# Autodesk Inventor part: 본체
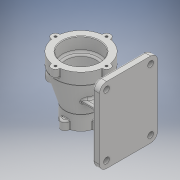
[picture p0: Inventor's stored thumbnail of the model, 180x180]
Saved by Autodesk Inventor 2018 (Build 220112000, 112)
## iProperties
Created: 2020-12
Part Number: 본체
Material: 일반
Document SubType Name: Modeling
Designer: home
Density: 1 g/cm^3
Appearance: 기본값
Author: home
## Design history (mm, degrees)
sketch "스케치1"
  geometry: L1 (0, 50)-(0, -50); L2 (32, 50)-(32, 30); L3 (29, 27)-(29, 27); L4 (26, 24)-(26, -17); L5 (23, -20)-(23, -20); L6 (20, -23)-(20, -50); L7 (32, 50)-(44, 50); L8 (44, 50)-(44, 30); L9 (20, -50)-(27.5, -50); L10 (27.5, -50)-(27.5, -25); L11 (27.5, -25)-(44, 30); A1 r 3 centre (29, 30) between (29, 27) and (32, 30); A2 r 3 centre (29, 24) between (29, 27) and (26, 24); A3 r 3 centre (23, -17) between (23, -20) and (26, -17); A4 r 3 centre (23, -23) between (23, -20) and (20, -23); 6 further points
  constraints: 22 end point, 8 point on circle, 8 point on line, 8 tangent, 4 centre point, 4 perpendicular, 3 horizontal, 3 vertical, 2 equal radius, 1 coincident, 1 midpoint
  dimensions: "d0" = 100 distance of L1.start L1.end; "d1" = 23 distance of L2.start point (32, 27); "d2" = 64 diameter of L2 L1; "d3" = 47 distance of point (26, 27) point (26, -20); "d4" = 30 distance of point (20, -20) L6.end; "d5" = 52 diameter of L4 L1; "d6" = 40 diameter of L6 L1; "d8" = 55 diameter of L9.end L1; "d9" = 88 diameter of L8 L1; "d10" = 25 distance of L9.end L10.end; "d11" = 20 distance of L7.end L8.end; "d12" = 50 distance from line of L7 point (0, 0); "d13" = 3 radius of A1; "d14" = 3 radius of A3 (derived)
revolve "회전1" sketch "스케치1" stored, may be unused: angle "d15" = 90 deg
node "작업 평면1"
sketch "스케치2"
  geometry: L1 (-38, 65)-(38, 65); L2 (50, 53)-(50, -53); L3 (38, -65)-(-38, -65); L4 (-50, -53)-(-50, 53); A1 r 12 centre (-38, 53) between (-38, 65) and (-50, 53); A2 r 12 centre (38, 53) between (50, 53) and (38, 65); A3 r 12 centre (38, -53) between (38, -65) and (50, -53); A4 r 12 centre (-38, -53) between (-50, -53) and (-38, -65); 6 further points
  constraints: 8 end point, 8 point on circle, 8 tangent, 6 point on line, 4 centre point, 3 equal radius, 2 midpoint, 2 parallel, 1 horizontal, 1 horizontal alignment, 1 perpendicular, 1 vertical alignment
  dimensions: "d17" = 100 distance of point (50, -65) point (-50, -65); "d18" = 130 distance of point (50, 65) point (50, -65); "d19" = 12 radius of A1 (derived)
extrude "돌출1" join sketch "스케치2" distance "d20" = 12; taper "d21" = 0 deg
sketch "스케치3"
  geometry: L1 (-25.725, -24)-(-73.725, -24); L2 (-38.725, 24)-(-73.725, 24); L3 (-73.725, 24)-(-73.725, -24); L4 (-25.725, -24)-(-38.725, 24); 1 further point
  constraints: 8 end point, 2 horizontal alignment, 1 vertical, 1 vertical alignment
  dimensions: "d24" = 24 distance from line of L2 point (0, 0); "d25" = 48 distance between parallel lines of L1 L2; "d26" = 48 distance of L1.start L1.end; "d27" = 35 distance of L2.start L2.end; "d29" = 73.72534 distance from line of L3 point (0, 0)
extrude "돌출2" join sketch "스케치3" stored distance "d30" = 8; taper "d31" = 0 deg
sketch "스케치5"
  geometry: L1 (21, 25)-(76, 25); L2 (76, 25)-(76, -25); L3 (76, -25)-(21, -25); C1 r 32 at (0, 0) reference; 1 further point
  constraints: 6 end point, 2 perpendicular, 1 horizontal, 1 vertical alignment
  dimensions: "d35" = 25 distance from line of L1 point (0, 0); "d36" = 50 distance between parallel lines of L3 L1; "d38" = 55 distance of L1.start L1.end; "d40" = 76 distance from line of L2 point (0, 0)
feature "리브1" sketch "스케치5" dims "d41" = 1, "d42" = 8, "d43" = 0, "d44" = 0, "d45" = 1, "d46" = 1
node "작업 평면2"
sketch "스케치6"
  geometry: C1 r 17 at (0, 0); 1 further point
  constraints: 1 centre point, 1 coincident
  dimensions: "d48" = 34 diameter of C1
extrude "돌출3" join sketch "스케치6" stored distance "d49" = 8; taper "d50" = 0 deg
sketch "스케치7"
  geometry: C1 r 17 at (0, 0) reference; 1 further point
  constraints: 1 coincident
hole "구멍1" sketch "스케치7" at (0, 0) diameter "d51" = 22; stored, may be unused: countersink angle "d55" = 90 deg, drill point angle "d57" = 118 deg; dims "d52" = 6, "d53" = 28, "d54" = 1, "d56" = 45
chamfer "모따기1" distance "d58" = 1; stored, may be unused: second distance "d59" = 2, angle "d60" = 45 deg
sketch "스케치8"
  geometry: C1 r 7 at (-44, 0); 1 further point
  constraints: 1 centre point, 1 horizontal alignment
  dimensions: "d61" = 14 diameter of C1; "d62" = 44 distance of C1.centre point (0, 0)
extrude "돌출4" join sketch "스케치8" distance "d63" = 15; taper "d64" = 0 deg
sketch "스케치9"
  geometry: 2 further points
  constraints: 1 horizontal alignment
  dimensions: "d65" = 44 distance of point (0, 0) point (44, 0)
hole "구멍2" sketch "스케치9" at (0, 0) diameter "d66" = 4.134; stored, may be unused: countersink angle "d70" = 90 deg, drill point angle "d72" = 118 deg; dims "d67" = 9, "d68" = 28, "d69" = 1, "d71" = 11
fillet "모깎기2" dims "d74" = 3
fillet "모깎기4" dims "d76" = 1
sketch "스케치11"
  geometry: C1 r 7 at (27.5, 0); 1 further point
  constraints: 1 centre point, 1 horizontal alignment
  dimensions: "d80" = 14 diameter of C1; "d81" = 27.5 distance of C1.centre point (0, 0)
extrude "돌출5" join sketch "스케치11" distance "d82" = 15; taper "d83" = 0 deg
fillet "모깎기5" dims "d84" = 3
fillet "모깎기6" dims "d85" = 1
sketch "스케치12"
  geometry: A1 r 7 centre (0, 0) between (-0.127, -6.999) and (-0.127, 6.999) reference; 1 further point
hole "구멍3" sketch "스케치12" at (0, 0) diameter "d86" = 4.134; stored, may be unused: countersink angle "d90" = 90 deg, drill point angle "d92" = 118 deg; dims "d87" = 9, "d88" = 28, "d89" = 1, "d91" = 11
fillet "모깎기7" dims "d96" = 1
chamfer "모따기2" distance "d97" = 1; stored, may be unused: second distance "d98" = 2, angle "d99" = 45 deg
fillet "모깎기8" dims "d100" = 3
sketch "스케치13"
  geometry: A1 r 12 centre (53, -38) between (53, -50) and (65, -38) reference; A2 r 12 centre (53, 38) between (65, 38) and (53, 50) reference; A3 r 12 centre (-53, 38) between (-53, 50) and (-65, 38) reference; A4 r 12 centre (-53, -38) between (-65, -38) and (-53, -50) reference; 1 further point
hole "구멍4" sketch "스케치13" at (53, -38), (53, 38), (-53, 38), (-53, -38) diameter "d101" = 10; stored, may be unused: countersink angle "d105" = 90 deg, drill point angle "d107" = 118 deg; dims "d102" = 9, "d103" = 28, "d104" = 1, "d106" = 10
fillet "모깎기9" dims "d108" = 3
fillet "모깎기10" dims "d109" = 3
fillet "모깎기11" dims "d110" = 3
fillet "모깎기12" dims "d111" = 3
sketch "스케치14"
  geometry: L1 (53, 50)-(-53, 50) reference; 2 further points
  constraints: 1 vertical alignment, 1 other
  dimensions: "d113" = 10 distance from line of L1 point (0, 40)
feature "엠보싱1" sketch "스케치14" dims "d0" = 100, "d1" = 23, "d2" = 64, "d3" = 47, "d4" = 30, "d5" = 52, "d6" = 40, "d8" = 55, "d9" = 88, "d10" = 25, "d11" = 20, "d12" = 50, "d13" = 3, "d14" = 3 (derived), "d114" = 0.5, "d115" = 0
fillet "모깎기13" dims "d116" = 3
node "솔리드1"
pattern_circular "원형 패턴1" dims "d78" = 360 deg
pattern_circular "원형 패턴2" dims "d94" = 360 deg
other parameters: "d16" = 82, "d47" = -45
